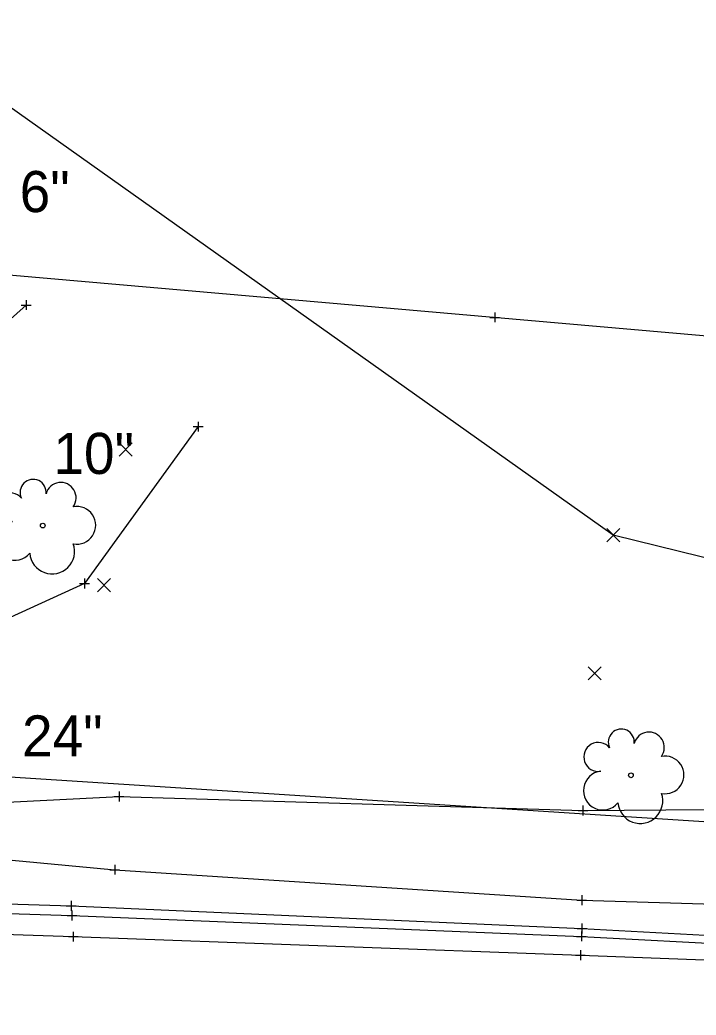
# Model space of a CAD drawing. Extents: x 2005176 to 2005823, y 572472 to 572942.
# Drawn here: x 2005571.3 to 2005639.9, y 572609.9 to 572710.8 of the extents above; entities that cross this region are included whole.
import ezdxf

# ---------------------------------------------------------------- set-up
doc = ezdxf.new("R2010")
doc.units = 0
for name, color, linetype in [('GE_X_Alignment_1000_Bearings', 7, 'Continuous'), ('GE_X_Alignment_1000_Cardinal_Points', 7, 'Continuous'), ('GE_X_Alignment_100_Bearings', 7, 'Continuous'), ('GE_X_Alignment_100_Distances', 7, 'Continuous'), ('GE_X_Alignment_100_Stations', 7, 'Continuous'), ('GE_X_Alignment_500_Bearings', 7, 'Continuous'), ('SC_Scratch10', 7, 'Continuous'), ('SC_Scratch8', 7, 'Continuous'), ('SV_P_Mon_Cells_Set', 7, 'Continuous'), ('SV_X_Random_Point', 7, 'Continuous'), ('SV_X_Shot_Marker', 7, 'Continuous'), ('SV_X_Terrain_Boundary', 7, 'Continuous'), ('UT_X_Overhead_Electric', 7, 'Continuous'), ('VG_X_Text', 7, 'Continuous')]:
    doc.layers.add(name, color=color, linetype=linetype)

msp = doc.modelspace()

# ---------------------------------------------------------------- linework, layer by layer
at = {"layer": 'GE_X_Alignment_1000_Bearings'}
msp.add_lwpolyline([(2005377.36, 572646.47), (2005740.51, 572623.1)], dxfattribs=at)
at = {"layer": 'GE_X_Alignment_1000_Cardinal_Points'}
msp.add_lwpolyline([(2005589.36, 572669.58), (2005577.83, 572653.68), (2005542.16, 572637.38), (2005475.27, 572632.41), (2005412.5, 572639.63), (2005455.37, 572649.17), (2005453.82, 572664.21)], dxfattribs=at)
at = {"layer": 'GE_X_Alignment_100_Bearings'}
msp.add_lwpolyline([(2005220.7, 572626.42), (2005272.19, 572624.71), (2005322.24, 572623.5), (2005370.59, 572622.7), (2005425.14, 572621.65), (2005477.36, 572620.84), (2005525.07, 572619.6), (2005576.7, 572617.86), (2005628.14, 572615.99), (2005678.39, 572614.09), (2005728.23, 572612.03), (2005777.04, 572611.02), (2005819.95, 572609.99)], dxfattribs=at)
at = {"layer": 'GE_X_Alignment_100_Distances'}
msp.add_lwpolyline([(2005220.68, 572626.38), (2005272.19, 572624.71), (2005322.24, 572623.5), (2005370.59, 572622.7), (2005425.14, 572621.65), (2005477.36, 572620.84), (2005525.07, 572619.6), (2005576.7, 572617.86), (2005628.14, 572615.99), (2005678.39, 572614.09), (2005728.23, 572612.03), (2005777.04, 572611.02), (2005820.02, 572609.9)], dxfattribs=at)
at = {"layer": 'GE_X_Alignment_100_Stations'}
msp.add_lwpolyline([(2005525.52, 572638.81), (2005532.8, 572636.84), (2005542.1, 572631.82), (2005552.86, 572627.27), (2005580.9, 572624.65), (2005628.27, 572621.55), (2005683.34, 572619.89), (2005735.02, 572617.81), (2005744.53, 572617.08)], dxfattribs=at)
at = {"layer": 'GE_X_Alignment_500_Bearings'}
for points in [[(2005540.28, 572656.58), (2005547.29, 572661.03), (2005560.54, 572671.8), (2005571.91, 572681.91)], [(2005563.28, 572631.16), (2005581.34, 572632.07), (2005628.4, 572630.65), (2005683.07, 572631.08), (2005734.76, 572630.65)]]:
    msp.add_lwpolyline(points, dxfattribs=at)
at = {"layer": 'SC_Scratch10'}
msp.add_lwpolyline([(2005220.88, 572629.15), (2005272.14, 572627.64), (2005321.83, 572626.68), (2005370.65, 572626), (2005424.7, 572625.92), (2005476.69, 572625.33), (2005525.49, 572622.56), (2005576.48, 572620.99), (2005628.3, 572618.68), (2005678.32, 572615.98), (2005728.35, 572614.83)], dxfattribs=at)
at = {"layer": 'SC_Scratch8'}
msp.add_lwpolyline([(2005220.9, 572628.72), (2005272.16, 572627.13), (2005321.83, 572625.74), (2005370.81, 572625), (2005424.98, 572624.56), (2005477.31, 572623.7), (2005525.21, 572621.63), (2005576.56, 572620.01), (2005628.24, 572617.89), (2005678.25, 572615.23), (2005728.27, 572613.25), (2005777.12, 572612.24), (2005820.02, 572611.5)], dxfattribs=at)
at = {"layer": 'SV_P_Mon_Cells_Set'}
for p, q in [((2005571.91, 572682.41), (2005571.91, 572681.41)), ((2005571.41, 572681.91), (2005572.41, 572681.91)), ((2005571.91, 572681.91), (2005571.91, 572681.91)), ((2005618.95, 572680.66), (2005619.95, 572680.66)), ((2005619.45, 572681.16), (2005619.45, 572680.16)), ((2005619.45, 572680.66), (2005619.45, 572680.66)), ((2005588.86, 572669.58), (2005589.86, 572669.58)), ((2005589.36, 572670.08), (2005589.36, 572669.08)), ((2005589.36, 572669.58), (2005589.36, 572669.58)), ((2005577.83, 572654.18), (2005577.83, 572653.18)), ((2005577.33, 572653.68), (2005578.33, 572653.68)), ((2005577.83, 572653.68), (2005577.83, 572653.68)), ((2005580.84, 572632.07), (2005581.84, 572632.07)), ((2005581.34, 572632.57), (2005581.34, 572631.57)), ((2005581.34, 572632.07), (2005581.34, 572632.07)), ((2005628.4, 572631.15), (2005628.4, 572630.15)), ((2005627.9, 572630.65), (2005628.9, 572630.65)), ((2005628.4, 572630.65), (2005628.4, 572630.65)), ((2005580.9, 572625.15), (2005580.9, 572624.15)), ((2005580.4, 572624.65), (2005581.4, 572624.65)), ((2005580.9, 572624.65), (2005580.9, 572624.65)), ((2005628.27, 572622.05), (2005628.27, 572621.05)), ((2005575.98, 572620.99), (2005576.98, 572620.99)), ((2005576.48, 572621.49), (2005576.48, 572620.49)), ((2005576.48, 572620.99), (2005576.48, 572620.99)), ((2005627.77, 572621.55), (2005628.77, 572621.55)), ((2005628.27, 572621.55), (2005628.27, 572621.55)), ((2005576.06, 572620.01), (2005577.06, 572620.01)), ((2005576.56, 572620.51), (2005576.56, 572619.51)), ((2005576.56, 572620.01), (2005576.56, 572620.01)), ((2005627.8, 572618.68), (2005628.8, 572618.68)), ((2005628.3, 572619.18), (2005628.3, 572618.18)), ((2005628.3, 572618.68), (2005628.3, 572618.68)), ((2005576.2, 572617.86), (2005577.2, 572617.86)), ((2005576.2, 572617.86), (2005577.2, 572617.86)), ((2005576.7, 572618.36), (2005576.7, 572617.36)), ((2005576.7, 572618.36), (2005576.7, 572617.36)), ((2005576.7, 572617.86), (2005576.7, 572617.86)), ((2005576.7, 572617.86), (2005576.7, 572617.86)), ((2005627.74, 572617.89), (2005628.74, 572617.89)), ((2005628.24, 572618.39), (2005628.24, 572617.39)), ((2005628.24, 572617.89), (2005628.24, 572617.89)), ((2005627.64, 572615.99), (2005628.64, 572615.99)), ((2005627.64, 572615.99), (2005628.64, 572615.99)), ((2005628.14, 572616.49), (2005628.14, 572615.49)), ((2005628.14, 572616.49), (2005628.14, 572615.49)), ((2005628.14, 572615.99), (2005628.14, 572615.99)), ((2005628.14, 572615.99), (2005628.14, 572615.99))]:
    msp.add_line(p, q, dxfattribs=at)
at = {"layer": 'SV_X_Random_Point'}
for p, q in [((2005581.35, 572666.6), (2005582.68, 572667.94)), ((2005581.35, 572667.94), (2005582.68, 572666.6)), ((2005630.82, 572657.91), (2005632.15, 572659.24)), ((2005630.82, 572659.24), (2005632.15, 572657.91)), ((2005579.14, 572652.84), (2005580.47, 572654.18)), ((2005579.14, 572654.18), (2005580.47, 572652.84)), ((2005628.92, 572643.89), (2005630.25, 572645.22)), ((2005628.92, 572645.22), (2005630.25, 572643.89))]:
    msp.add_line(p, q, dxfattribs=at)
at = {"layer": 'SV_X_Shot_Marker'}
for centre in [(2005573.6, 572659.54), (2005633.27, 572634.22)]:
    msp.add_circle(centre, 0.24, dxfattribs=at)
for centre, radius, start, end in [((2005572.62, 572662.91), 1.32, 354.0047, 205.9741), ((2005575.43, 572662.37), 1.55, 323.83, 165.0376), ((2005570.29, 572661.4), 1.47, 39.0625, 279.5412), ((2005577.06, 572659.57), 1.91, 259.1453, 101.4596), ((2005570.75, 572657.99), 1.97, 96.1722, 320.5737), ((2005574.55, 572656.93), 2.28, 184.9476, 19.4572), ((2005632.29, 572637.59), 1.32, 354.0047, 205.9741), ((2005635.1, 572637.05), 1.55, 323.83, 165.0376), ((2005629.96, 572636.08), 1.47, 39.0625, 279.5412), ((2005636.73, 572634.26), 1.91, 259.1453, 101.4596), ((2005630.42, 572632.67), 1.97, 96.1722, 320.5737), ((2005634.22, 572631.62), 2.28, 184.9476, 19.4572)]:
    msp.add_arc(centre, radius, start, end, dxfattribs=at)
at = {"layer": 'SV_X_Terrain_Boundary'}
msp.add_lwpolyline([(2005682.42, 572646.03), (2005631.48, 572658.58), (2005562.59, 572707.41), (2005552.72, 572710.82), (2005513.74, 572704), (2005498.99, 572705.6), (2005481.51, 572691.94), (2005424.05, 572668.06)], dxfattribs=at)
at = {"layer": 'UT_X_Overhead_Electric'}
msp.add_line((2005462.76, 572694.31), (2005730.63, 572670.98), dxfattribs=at)

# ---------------------------------------------------------------- texts
at = {"layer": 'VG_X_Text'}
for s, p in [('6"', (2005571.26, 572691.33)), ('10"', (2005574.68, 572664.78)), ('24"', (2005571.5, 572636.13))]:
    msp.add_text(s, height=4.167, dxfattribs=at).set_placement(p)

doc.saveas('drawing.dxf')
